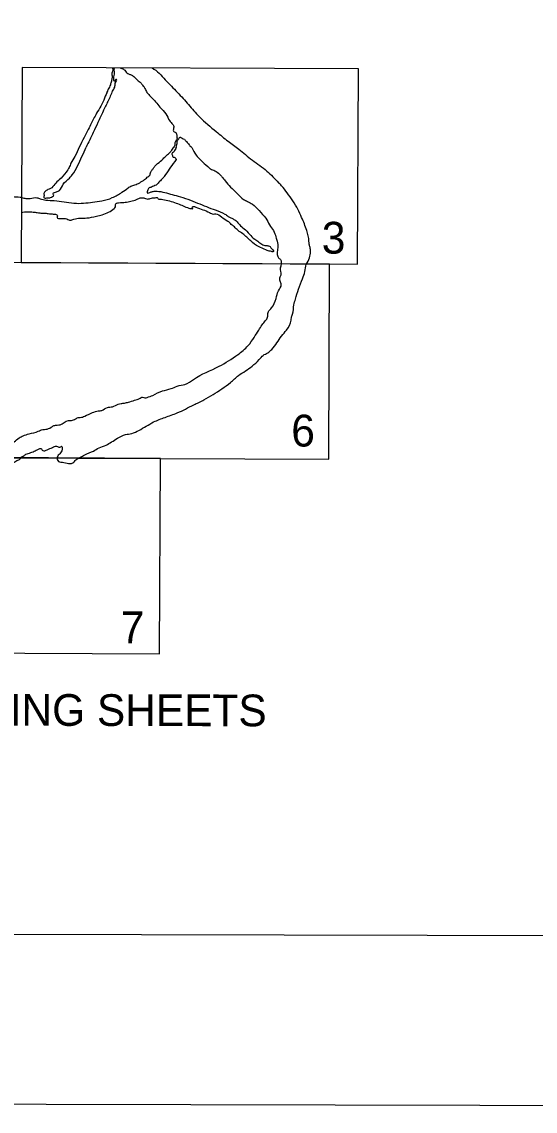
# Model space of a CAD drawing. Extents: x 3177385 to 3215275, y 903885 to 929304.
# Drawn here: x 3203387 to 3205274, y 904468 to 908477 of the extents above; entities that cross this region are included whole.
import ezdxf

# ---------------------------------------------------------------- set-up
doc = ezdxf.new("R2010")
doc.units = 0
for name, color, linetype in [('G-ANNO-NPLT', 7, 'Continuous'), ('V-ANNO-NPLT', 7, 'Continuous'), ('V-ANNO-SYMB', 7, 'Continuous')]:
    doc.layers.add(name, color=color, linetype=linetype)

msp = doc.modelspace()

# ---------------------------------------------------------------- linework, layer by layer
at = {"layer": 'G-ANNO-NPLT'}
msp.add_lwpolyline([(3177968.5, 904553.8), (3214635.1, 904468.5), (3214691.3, 928635.1), (3178024.7, 928720.4)], close=True, dxfattribs=at)
at = {"layer": 'V-ANNO-NPLT'}
for points in [[(3204621, 907585.3), (3204624, 908303.8), (3203387.6, 908309.4), (3203384, 907591), (3204621, 907585.3)], [(3203277.3, 906873.1), (3204514.9, 906867.4), (3204517.9, 907585.8), (3203280.9, 907591.5), (3203277.3, 906873.1)], [(3202654.5, 906158.1), (3203892.7, 906151.7), (3203896.1, 906870.1), (3203277.3, 906873.3)]]:
    msp.add_lwpolyline(points, dxfattribs=at)
for points in [[(3203719.2, 908307.7), (3203719.8, 908306.5), (3203721.6, 908298), (3203718.3, 908291.5), (3203717.8, 908284.9), (3203718.3, 908271.3), (3203715.9, 908258.6), (3203712.1, 908245), (3203704.6, 908229), (3203698.4, 908216.4)], [(3203720, 908222.4), (3203728, 908237), (3203730.4, 908251), (3203734.2, 908259.5), (3203735.1, 908264.7), (3203733.7, 908265.1), (3203730.9, 908263.7), (3203729.5, 908260.4), (3203726.7, 908258.6), (3203725.3, 908260.5), (3203725.3, 908264.7), (3203725.3, 908268.4), (3203726.3, 908279.7), (3203727.7, 908288.6), (3203726.8, 908293.8), (3203726.3, 908299.4), (3203726.8, 908303.7), (3203726.3, 908307), (3203726.1, 908307.9)], [(3203747.7, 908308.1), (3203754.5, 908305), (3203761, 908302.2), (3203764.8, 908298.9), (3203770.4, 908291.8), (3203776, 908286.6), (3203786.3, 908282.9), (3203795.2, 908277.7), (3203805.6, 908268.7), (3203818.2, 908257.4), (3203825.2, 908251.3), (3203828.5, 908246.6), (3203833.2, 908240.5), (3203839.3, 908232), (3203843, 908224.9), (3203846.7, 908216.9)], [(3203865.1, 908307.4), (3203865.3, 908307.3), (3203914.2, 908263.4), (3203958.9, 908217.4), (3203999.4, 908172.5), (3204039.8, 908127.5), (3204101.5, 908072.9), (3204145.2, 908037.6), (3204184.6, 908008.7)], [(3203701.4, 908222.4), (3203690.9, 908196.6), (3203676.7, 908166.6), (3203661.6, 908140.3), (3203650.3, 908119.7), (3203636.2, 908091.5), (3203615.4, 908051.2), (3203597.5, 908015.5)], [(3203720.1, 908222.5), (3203703, 908184.4), (3203685.1, 908147.8), (3203666.3, 908106.5), (3203649.3, 908069.9), (3203622.9, 908015.4)], [(3203846.7, 908216.9), (3203859.8, 908202.8), (3203878.6, 908182.1), (3203894.5, 908163.3), (3203916, 908137.9), (3203930, 908113.4), (3203941.3, 908099.3), (3203944.1, 908095.5), (3203944, 908081.4), (3203944, 908074.8), (3203950.6, 908071.1), (3203954.3, 908067.3), (3203956.2, 908060.7), (3203956.2, 908055.1), (3203957.1, 908052.3), (3203956.2, 908045.7), (3203953.3, 908039.1), (3203950.5, 908034.4), (3203948.6, 908023.1), (3203943.9, 908014.7)], [(3203954.2, 908014.7), (3203957, 908025), (3203958, 908033.5), (3203959, 908040), (3203961.8, 908043.8), (3203965.5, 908049.4), (3203968.4, 908052.2), (3203971.2, 908051.3), (3203975.9, 908048.5), (3203984.3, 908044.7), (3203991.8, 908036.2), (3203997.4, 908030.5), (3204002.1, 908024.9), (3204004.9, 908021.1), (3204011.5, 908014.5)], [(3203597.5, 908015.5), (3203581.5, 907981.7), (3203567.3, 907956.4), (3203560.7, 907941.4), (3203549.4, 907923.5), (3203524, 907895.4), (3203508, 907879.5), (3203492, 907863.5), (3203482.6, 907859.8), (3203470.4, 907850.4), (3203467.6, 907844.8), (3203468.5, 907840.1), (3203467.6, 907834.5), (3203467.6, 907830.7), (3203478.8, 907828.8), (3203492, 907830.6), (3203499.5, 907834.4), (3203504.2, 907839.1), (3203502.3, 907842.8), (3203501.4, 907845.7), (3203507, 907848.5), (3203514.5, 907851.3), (3203524.9, 907856.9), (3203539, 907879.4), (3203561.6, 907901.9), (3203571.9, 907914.1), (3203607.8, 907981.7), (3203622.9, 908015.4)], [(3203954.2, 908014.7), (3203946.2, 908000.1), (3203940.5, 907994.5), (3203937.7, 907991.7), (3203939.6, 907987), (3203940.5, 907982.3), (3203943.3, 907978.5), (3203946.1, 907978.5), (3203950.8, 907976.6), (3203953.6, 907971), (3203948.9, 907962.5), (3203910.3, 907908.1), (3203901.8, 907897.8), (3203890.5, 907886.6), (3203885.8, 907880.9), (3203880.2, 907876.3), (3203871.7, 907872.5), (3203863.3, 907868.8), (3203852.9, 907864.1), (3203850.1, 907858.5), (3203847.3, 907851), (3203847.3, 907847.2), (3203853.8, 907848.1), (3203864.2, 907851.9), (3203876.4, 907853.7), (3203932.7, 907843.2), (3203960.8, 907835.7), (3204033, 907810.1), (3204097.7, 907784.6), (3204133.4, 907769.5), (3204145.6, 907761)], [(3203858.2, 907913.4), (3203862.5, 907928), (3203869.1, 907936.4), (3203875.7, 907945.8), (3203886, 907955.2), (3203905.8, 907973), (3203918.9, 907985.2), (3203933, 907998.3), (3203935.9, 908002), (3203940.6, 908008.6), (3203944.6, 908016)], [(3204011.5, 908014.5), (3204027.8, 907986.8), (3204044.7, 907968), (3204070, 907944.4), (3204080.3, 907935.9), (3204096.2, 907929.3), (3204113.1, 907916.1), (3204122.4, 907906.7), (3204134.6, 907891.6), (3204153.3, 907869)], [(3204184.6, 908008.7), (3204234.3, 907968.5), (3204287.7, 907927.9), (3204330.3, 907885.1)], [(3203386.6, 907830.5), (3203400.9, 907827.1), (3203416.9, 907827.1), (3203442.2, 907829.8), (3203454.4, 907826), (3203475, 907821.3), (3203506, 907819.3), (3203541.7, 907814.6), (3203578.3, 907809.8), (3203613.9, 907809.7), (3203646.8, 907813.4), (3203680.6, 907818), (3203719.1, 907830.1), (3203754.8, 907849.8), (3203777.4, 907865.7), (3203784, 907870.4), (3203798.1, 907876), (3203815, 907882.5), (3203833.8, 907893.7), (3203847.9, 907905), (3203858.2, 907913.4)], [(3204432.5, 907585.1), (3204444.2, 907608.5), (3204448, 907632), (3204446.1, 907647.1), (3204443.3, 907658.4), (3204442.4, 907669.6), (3204434.1, 907709.1), (3204415.4, 907757.1), (3204401.4, 907787.2), (3204362.1, 907847.4), (3204341.5, 907873.8), (3204330.3, 907885.1)], [(3203386.6, 907830.5), (3203360.3, 907832), (3203327.2, 907834.8), (3203298.2, 907837.6), (3203273.3, 907834.9), (3203255.4, 907833.6), (3203240.2, 907828.1), (3203233.2, 907826.7), (3203225, 907828.1), (3203139.3, 907833.9), (3203104.8, 907832.6), (3203068.9, 907832.6), (3203028.9, 907835.5), (3202986.1, 907838.4), (3202946, 907842.6), (3202860.4, 907838.7), (3202810.6, 907831.9), (3202781.6, 907830.5), (3202737.4, 907825.1), (3202687.7, 907825.2), (3202649, 907825.3), (3202624.2, 907825.4), (3202599.3, 907828.2), (3202555.1, 907821.4)], [(3204153.3, 907869), (3204178.6, 907845.5), (3204201.1, 907823.8), (3204216.1, 907816.3), (3204234.8, 907805.9), (3204259.2, 907782.3), (3204283.5, 907754.1), (3204297.5, 907729.6), (3204311.6, 907708.9), (3204320.9, 907685.4), (3204325.6, 907669.4), (3204327.4, 907645), (3204325.5, 907626.2), (3204326.4, 907616.8), (3204332.9, 907606.5), (3204339.5, 907598), (3204339.5, 907593.3), (3204341.6, 907586.4)], [(3203384.3, 907776), (3203408.3, 907778.2), (3203428, 907777.2), (3203443, 907775.3), (3203461.8, 907772.5), (3203475.9, 907772.4), (3203491.8, 907770.5), (3203505.9, 907769.5), (3203515.3, 907766.7), (3203517.2, 907762.9), (3203516.2, 907756.4), (3203521.8, 907753.5), (3203532.1, 907753.5), (3203551.9, 907751.6), (3203559.4, 907747.8), (3203570.6, 907747.8), (3203578.1, 907750.6), (3203625.1, 907755.2), (3203660.8, 907761.7), (3203682.4, 907767.2), (3203705.8, 907776.6), (3203725.6, 907789.7), (3203731.2, 907796.3), (3203732.2, 907807.5), (3203742.5, 907811.3), (3203766.9, 907813.1), (3203787.6, 907816.8), (3203808.3, 907823.3), (3203826.1, 907829.9), (3203837.4, 907828), (3203845.8, 907825.1), (3203859, 907827), (3203866.5, 907828.8)], [(3203866.5, 907828.8), (3203880.1, 907830.2), (3203884.8, 907830.2), (3203887.6, 907825.5), (3203894.2, 907824.5), (3203904.5, 907823.6), (3203954.2, 907810.3), (3203995.5, 907793.3), (3204004.8, 907790.5), (3204011.4, 907789.5), (3204015.2, 907789.5), (3204013.3, 907794.2), (3204016.1, 907797), (3204026.4, 907795.1), (3204077.1, 907775.2), (3204090.2, 907769.6), (3204099.6, 907770.5), (3204121.2, 907759.2), (3204143.6, 907744.1)], [(3204145.6, 907761), (3204163.4, 907751.6), (3204175.6, 907744), (3204186.8, 907730.8), (3204203.7, 907715.8), (3204223.3, 907696), (3204243, 907677.1), (3204258, 907666.8), (3204273, 907656.4), (3204288, 907653.5), (3204299.2, 907649.8), (3204305.8, 907641.3), (3204311.4, 907634.7), (3204311.4, 907631.9), (3204301.1, 907632.8), (3204292.6, 907633.8), (3204284.2, 907637.6), (3204257, 907649.9), (3204228, 907670.6), (3204198.9, 907697), (3204182, 907709.2), (3204168, 907722.4), (3204156.8, 907731.8), (3204151.1, 907737.5), (3204143.6, 907744.1)], [(3204240.7, 907315.8), (3204257.5, 907341.9), (3204270.1, 907361.7), (3204282.6, 907377.4), (3204290, 907389.9), (3204291, 907399.3), (3204292.1, 907407.7), (3204299.4, 907418.1), (3204304.7, 907424.4), (3204321.5, 907458.8), (3204329.9, 907487.1), (3204340.4, 907510), (3204336.3, 907522.6), (3204336.3, 907538.3), (3204340.5, 907548.7), (3204338.4, 907558.2), (3204341.6, 907586.4)], [(3204341, 907320.8), (3204359.9, 907342.7), (3204376.7, 907379.2), (3204377.7, 907387.6), (3204381.9, 907401.2), (3204387.2, 907435.7), (3204392.5, 907456.6), (3204404.1, 907493.2), (3204418.8, 907531.8), (3204427.2, 907557.9), (3204432.5, 907585.1)], [(3203868.3, 907102.2), (3203903.9, 907118.9), (3203935.2, 907127.2), (3203957.2, 907136.5), (3203986.5, 907142.8), (3204017.8, 907161.5), (3204112, 907209.4), (3204180, 907252.1), (3204218.7, 907285.5), (3204240.7, 907315.8)], [(3203871.2, 907005), (3203913.1, 907021.6), (3203958, 907038.2), (3204018.7, 907067.4), (3204056.3, 907086.1), (3204122.2, 907126.8), (3204153.6, 907149.7), (3204182.9, 907175.8), (3204209.1, 907192.4), (3204233.2, 907210.2), (3204259.3, 907234.1), (3204274, 907249.8), (3204290.7, 907259.2), (3204305.4, 907271.7), (3204341, 907320.8)], [(3203294.5, 906877.6), (3203301.6, 906883.9), (3203303.7, 906886), (3203304.8, 906891.3), (3203312.1, 906897.5), (3203324.7, 906906.9), (3203338.3, 906920.5), (3203358.1, 906931.9), (3203377, 906946.5), (3203391.6, 906953.8), (3203413.5, 906961), (3203447, 906970.4), (3203463.8, 906976.6), (3203475.2, 906977.7), (3203494.1, 906984.9), (3203504.5, 906991.2), (3203517.1, 906993.3), (3203527.5, 906994.3), (3203557.8, 907009.9), (3203569.3, 907009.9), (3203584, 907016.1), (3203596.5, 907021.3), (3203601.7, 907021.3), (3203617.7, 907026), (3203646.7, 907039), (3203667.6, 907045.2), (3203681.2, 907047.3), (3203701.1, 907057.7), (3203719.9, 907060.8), (3203741.2, 907070.1), (3203751.3, 907072.2), (3203763.8, 907074.3), (3203778.4, 907077.4), (3203801.4, 907084.6), (3203819.2, 907090.9), (3203830.7, 907096.1), (3203839.1, 907093.9), (3203847.4, 907095), (3203868.3, 907102.2)], [(3203390.8, 906877.3), (3203401.9, 906885.8), (3203410.3, 906888.9), (3203428, 906895.2), (3203442.7, 906902.4), (3203453.1, 906906.6), (3203458.4, 906905.5), (3203461.5, 906901.4), (3203467.7, 906898.2), (3203479.2, 906902.4), (3203499.1, 906910.7), (3203514.2, 906915.6), (3203526.3, 906911.7), (3203532.8, 906915.1), (3203534.6, 906904.3), (3203526.2, 906887.6), (3203516.9, 906875.6), (3203521.3, 906859.4), (3203529.8, 906857), (3203552.8, 906853.3), (3203574.2, 906853.7), (3203585.7, 906865.5), (3203600.4, 906873.8), (3203618.1, 906884.3), (3203650.6, 906897.8), (3203670.4, 906909.2), (3203696.6, 906919.6), (3203716.4, 906931.1), (3203738.4, 906944.6), (3203767.7, 906958.2), (3203790.7, 906962.3), (3203816.8, 906973.7), (3203871.2, 907005)], [(3203390.8, 906877.3), (3203384.6, 906874), (3203382.3, 906870.2), (3203376.3, 906865.8), (3203344.8, 906847.8), (3203312.6, 906832.2), (3203308.8, 906829.2), (3203305.1, 906823.2), (3203303.6, 906818.7), (3203302.8, 906815.7), (3203296.8, 906812), (3203276.6, 906794), (3203260.8, 906776.8), (3203250.3, 906767.1), (3203241.3, 906759.6), (3203233, 906752.1), (3203216.5, 906730.4), (3203209.7, 906719.2), (3203207.5, 906711.7), (3203206.7, 906708), (3203203, 906701.2), (3203197.7, 906698.2), (3203194, 906697.5), (3203189.5, 906696.8), (3203186.5, 906692.3), (3203161.7, 906657.8), (3203157.1, 906647.4), (3203150.5, 906636.1)]]:
    msp.add_spline(points, degree=3, dxfattribs=at)
at = {"layer": 'V-ANNO-SYMB'}
msp.add_lwpolyline([(3180720.1, 905172.5), (3213803.2, 905095.5), (3213856.5, 928012), (3180773.4, 928089), (3180720.1, 905172.5)], dxfattribs=at)

# ---------------------------------------------------------------- texts
at = {"layer": 'V-ANNO-NPLT'}
for s, height, p in [('3', 117, (3204489.2, 907624.1)), ('6', 117, (3204377, 906914.4)), ('7', 117, (3203749.8, 906190.6)), ('INDEX TO ADJOINING SHEETS', 116.66, (3201989.8, 905890.1))]:
    msp.add_text(s, height=height, rotation=359.8667, dxfattribs=at).set_placement(p)

doc.saveas('drawing.dxf')
